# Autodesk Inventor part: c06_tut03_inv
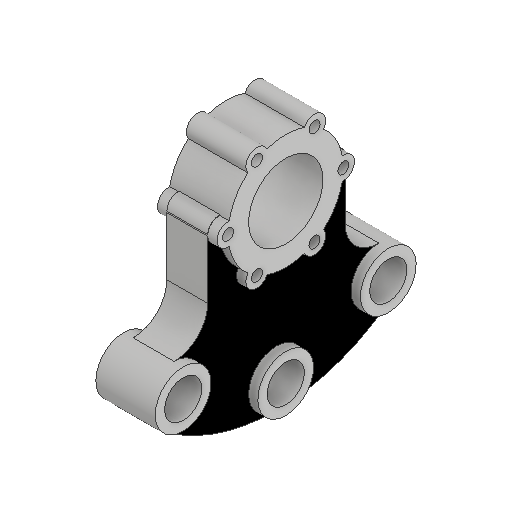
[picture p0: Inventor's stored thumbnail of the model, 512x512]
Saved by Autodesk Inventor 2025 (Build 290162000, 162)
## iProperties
Created: 2015-03
Part Number: c06_tut03_inv
Material: Generic
Document SubType Name: Modeling
Designer: Sandeep
Density: 1 g/cm^3
Appearance: Default
Author: Sandeep
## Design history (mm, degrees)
sketch "Sketch1"
  geometry: L1 (-37, -31.635)-(-37, 0.365); L2 (0, 14.952)-(0, -99.335); L3 (37, 0.365)-(37, -31.635); L4 (-55.203, -64.635)-(-64.945, -76.041); L5 (55.203, -64.635)-(64.945, -76.041); L6 (0, 0)-(41.78, 0); A1 r 31 centre (0, 0) between (30.347, 6.33) and (-30.347, 6.33); A2 r 18 centre (-55, -31.635) between (-55.111, -49.635) and (-37, -31.635); A3 r 15 centre (-55.203, -64.635) between (-55.111, -49.635) and (-64.945, -76.041); A4 r 100 centre (0, 0) between (-64.945, -76.041) and (64.945, -76.041); A5 r 18 centre (55, -31.635) between (37, -31.635) and (55.111, -49.635); A6 r 15 centre (55.203, -64.635) between (64.945, -76.041) and (55.111, -49.635); A7 r 6 centre (-31, 0.365) between (-30.347, 6.33) and (-37, 0.365); A8 r 6 centre (31, 0.365) between (37, 0.365) and (30.347, 6.33); 1 further point
  constraints: 16 point on circle, 12 end point, 8 centre point, 7 tangent, 3 vertical, 2 coincident, 2 symmetric about line, 1 horizontal, 1 parallel, 1 point on line, 3 other
  dimensions: "d0" = 31 radius of A1; "d2" = 18 radius of A5; "d3" = 15 radius of A6; "d4" = 100 radius of A4; "d6" = 81 deg angle of L5 L4; "d7" = 65 vertical distance of L3.start L5.start; "d8" = 6 radius of A7; "d10" = 74 distance between parallel lines of L3 L1
extrude "Extrusion1" new body sketch "Sketch1" stored distance "d11" = 22; taper "d12" = 0 deg
sketch "Sketch5"
  geometry: L1 (0, 48.219)-(0, -124.115); L2 (0, 0)-(43.472, 0); L3 (0, 0)-(17.524, 30.352); A1 r 6 centre (31.011, 0) between (30.42, -5.971) and (30.42, 5.971); A2 r 31 centre (0, 0) between (30.347, 6.33) and (-30.347, 6.33) reference; A3 r 6 centre (15.5, 26.847) between (20.381, 23.358) and (10.038, 29.33); A4 r 31 centre (0, 0) between (30.42, 5.971) and (20.381, 23.358); A5 r 6 centre (-31.011, 0) between (-30.42, 5.971) and (-30.42, -5.971); A6 r 6 centre (-15.5, 26.847) between (-10.038, 29.33) and (-20.381, 23.358); A7 r 6 centre (-15.5, -26.847) between (-20.381, -23.358) and (-10.038, -29.33); A8 r 6 centre (15.5, -26.847) between (10.038, -29.33) and (20.381, -23.358); A9 r 31 centre (0, 0) between (10.038, 29.33) and (-10.038, 29.33); A10 r 31 centre (0, 0) between (-20.381, 23.358) and (-30.42, 5.971); A11 r 31 centre (0, 0) between (-30.42, -5.971) and (-20.381, -23.358); A12 r 31 centre (0, 0) between (-10.038, -29.33) and (10.038, -29.33); A13 r 31 centre (0, 0) between (20.381, -23.358) and (30.42, -5.971); 2 further points
  constraints: 28 point on circle, 12 centre point, 12 symmetric about line, 6 end point, 3 point on line, 1 coincident, 1 horizontal, 1 vertical, 4 other
  dimensions: "d19" = 12 diameter of A1; "d20" = 60 deg angle of L2 L3; "d21" = 12 diameter of A3
extrude "Extrusion2" join sketch "Sketch5" stored distance "d22" = 32; taper "d23" = 0 deg
hole "Hole1" diameter "d26" = 6; stored, may be unused: countersink angle "d30" = 90 deg, drill point angle "d32" = 118 deg; dims "d24" = 10, "d25" = 10, "d27" = 6, "d28" = 4, "d29" = 2, "d31" = 8
pattern_circular "Circular Pattern1" dims angle "d34" = 360 deg
sketch "Sketch6"
  geometry: A1 r 15 centre (-55.203, -64.635) between (-55.111, -49.635) and (-64.945, -76.041) reference; 2 further points
  constraints: 1 coincident, 3 other
extrude "Extrusion3" join sketch "Sketch6" stored distance "d36" = 32; taper "d37" = 0 deg
hole "Hole2" diameter "d40" = 20; stored, may be unused: countersink angle "d44" = 90 deg, drill point angle "d46" = 118 deg; dims "d41" = 6, "d42" = 4, "d43" = 2, "d45" = 8, "d59" = 10, "d60" = 10
pattern_circular "Circular Pattern2" dims "d48" = 81 deg
hole "Hole3" diameter "d52" = 40; stored, may be unused: countersink angle "d56" = 90 deg, drill point angle "d58" = 118 deg; dims "d50" = 10, "d51" = 10, "d53" = 6, "d54" = 4, "d55" = 2, "d57" = 8
body "Solid1"
other parameters: "d18" = 62
